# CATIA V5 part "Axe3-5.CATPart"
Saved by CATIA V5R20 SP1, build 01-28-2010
Part number: Axe3-5
Bounding box of the stored display mesh (mm): x -20.149 to 60.141, y 170.435 to 187.07, z -7.312 to 7.312
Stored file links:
  C:\Users\RENARD Simon\Documents\Cours IFMA\2ème année\IAO\Axe3-5.CATPart
  C:\Users\RENARD Simon\Documents\Cours IFMA\2ème année\IAO\Trainattero.CATProduct
  C:\Users\RENARD Simon\Documents\Cours IFMA\2ème année\IAO\Piece3.CATPart
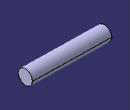
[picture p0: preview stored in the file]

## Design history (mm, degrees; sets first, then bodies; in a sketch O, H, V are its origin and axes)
Set1
  DatumSurface1: linked copy from another document
  Line1: linked copy from another document
Body1 (main body)
  Sketch1 on face of DatumSurface1, origin (56.3198, -1.1534, 0), H (0.0205, 0.9998, 0), V (0, 0, 1)
    circle A1 centre (179.1245, 0) radius 7.5
    point P1 (179.1245, 0)
    point P2 (171.6245, 0)
    reference projected point E1 (179.1245, 0) from Line1
    radius A1 = 7.5
    coincidence: P1 H, A1 P2, P2 H, P1 E1
  Pad1: profile Sketch1, direction (-0.9998, 0.0205, 0), length 80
